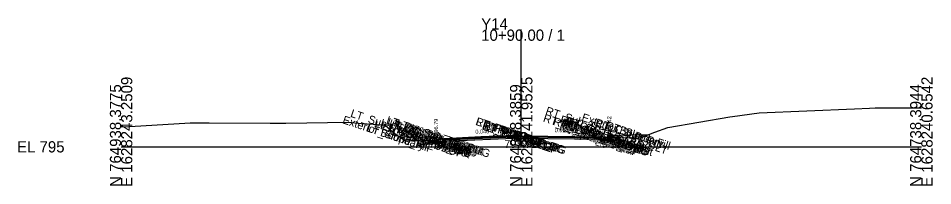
# Model space of a CAD drawing. Extents: x -26 to 1403, y -10 to 4517.
# Drawn here: x 1174.3 to 1402.8, y -9.7 to 32.1 of the extents above; entities that cross this region are included whole.
import ezdxf

# ---------------------------------------------------------------- set-up
doc = ezdxf.new("R2010")
doc.units = 0
for name, color, linetype in [('Default', 7, 'Continuous'), ('Exist CMT Pavement', 7, 'Continuous'), ('Exist Cross Section Cell', 7, 'Continuous'), ('Exist XS Center Line Elevation Label', 7, 'Continuous'), ('Exist XS Ground Line', 7, 'Continuous'), ('Prop CMT Conc Surface', 7, 'Continuous'), ('Prop CMT Concrete Structures', 7, 'Continuous'), ('Prop CMT Pvmt Course 1', 7, 'Continuous'), ('Prop CMT Pvmt Course 1 CG', 7, 'Continuous'), ('Prop CMT Pvmt Course 1 Wedge', 7, 'Continuous'), ('Prop CMT Pvmt Course 2', 7, 'Continuous'), ('Prop CMT Pvmt Course 2 Wedge', 7, 'Continuous'), ('Prop CMT Pvmt Course 3', 7, 'Continuous'), ('Prop CMT Pvmt Course 3 Wedge', 7, 'Continuous'), ('Prop CMT Pvmt Surface', 7, 'Continuous'), ('Prop CMT Pvmt Wedge Surface 1', 7, 'Continuous'), ('Prop CMT Pvmt Wedge Surface 2', 7, 'Continuous'), ('Prop CMT Pvmt Wedge Surface 3', 7, 'Continuous'), ('Prop CMT Slope Grass', 7, 'Continuous'), ('Prop CMT Subgrade Earthwork', 7, 'Continuous'), ('Prop XS Hydro Elevations', 7, 'Continuous'), ('Prop XS SE Text', 7, 'Continuous'), ('Scratch_Level_0', 7, 'Continuous')]:
    doc.layers.add(name, color=color, linetype=linetype)

msp = doc.modelspace()

# ---------------------------------------------------------------- linework, layer by layer
at = {"layer": 'Exist CMT Pavement'}
for points in [[(1300, 2.72), (1296.27, 2.75), (1289.94, 2.52), (1280.71, 2.02)], [(1300, 2.72), (1319.98, 2.52)]]:
    msp.add_lwpolyline(points, dxfattribs=at)
at = {"layer": 'Exist Cross Section Cell'}
for p, q in [((1300, 0), (1300, 29.25)), ((1200, 0), (1300, 0)), ((1300, 0), (1400, 0))]:
    msp.add_line(p, q, dxfattribs=at)
at = {"layer": 'Exist XS Ground Line'}
msp.add_lwpolyline([(1200, 4.98), (1202.22, 5.06), (1217.27, 5.96), (1221.97, 5.97), (1237.27, 5.88), (1241.16, 5.94), (1256.85, 6.11), (1260.03, 5.8), (1262.96, 5.64), (1266.02, 5.41), (1268.47, 3.22), (1270.61, 1.81), (1274.23, 1.49), (1277.23, 1.59), (1280.71, 2.02), (1289.94, 2.52), (1296.27, 2.75), (1300, 2.72), (1304.27, 2.67), (1319.98, 2.52), (1329.42, 2.12), (1329.8, 2.27), (1333.43, 3.65), (1336.63, 4.78), (1352.12, 7.46), (1352.8, 7.54), (1359.49, 8.5), (1383.26, 9.46), (1387.07, 9.68), (1388.46, 9.69), (1400, 9.75)], dxfattribs=at)
at = {"layer": 'Prop CMT Conc Surface'}
for points in [[(1278.71, 1.79), (1278.71, 2.29), (1278.21, 2.29)], [(1319.98, 2.52), (1321.98, 2.42)], [(1321.98, 2.42), (1321.98, 2.92), (1322.48, 2.92)], [(1280.71, 1.95), (1278.71, 1.79)]]:
    msp.add_lwpolyline(points, dxfattribs=at)
at = {"layer": 'Prop CMT Concrete Structures'}
for points in [[(1280.71, 1.95), (1278.71, 1.79), (1278.71, 2.29), (1278.21, 2.29)], [(1278.21, 2.29), (1278.21, 1.26), (1280.71, 1.36)], [(1319.98, 2.52), (1321.98, 2.42), (1321.98, 2.92), (1322.48, 2.92)], [(1322.48, 2.92), (1322.48, 1.91), (1319.98, 1.94)], [(1319.98, 1.94), (1319.98, 2.52)], [(1280.71, 1.36), (1280.71, 1.95)]]:
    msp.add_lwpolyline(points, dxfattribs=at)
at = {"layer": 'Prop CMT Pvmt Course 1'}
for points in [[(1300, 2.72), (1280.71, 1.95)], [(1280.71, 1.82), (1300, 2.59)], [(1300, 2.47), (1300, 2.72)], [(1300, 2.72), (1319.98, 2.52)], [(1300, 2.47), (1300, 2.72)], [(1300, 2.59), (1300, 2.47), (1300, 2.47)], [(1319.98, 2.4), (1300, 2.59)], [(1300, 2.59), (1300, 2.47), (1300, 2.47)], [(1319.98, 2.52), (1319.98, 2.27), (1319.98, 2.27), (1319.98, 2.4)], [(1280.71, 1.95), (1280.71, 1.7), (1280.71, 1.7), (1280.71, 1.82)]]:
    msp.add_lwpolyline(points, dxfattribs=at)
at = {"layer": 'Prop CMT Pvmt Course 1 CG'}
for points in [[(1280.71, 1.36), (1277.71, 1.24), (1277.36, 0.9)], [(1277.36, 0.9), (1280.71, 1.03)], [(1280.71, 1.03), (1280.71, 1.36)], [(1319.98, 1.94), (1322.98, 1.91), (1323.31, 1.57)], [(1319.98, 1.6), (1319.98, 1.94)], [(1323.31, 1.57), (1319.98, 1.6)]]:
    msp.add_lwpolyline(points, dxfattribs=at)
at = {"layer": 'Prop CMT Pvmt Course 1 Wedge'}
for points in [[(1300, 2.59), (1280.71, 1.82)], [(1300, 2.59), (1319.98, 2.4)]]:
    msp.add_lwpolyline(points, dxfattribs=at)
at = {"layer": 'Prop CMT Pvmt Course 2'}
for points in [[(1280.71, 1.36), (1280.71, 1.36), (1280.71, 1.7), (1280.71, 1.7)], [(1280.71, 1.7), (1280.71, 1.36)], [(1319.98, 1.94), (1319.98, 1.94), (1319.98, 2.27), (1319.98, 2.27)], [(1319.98, 2.27), (1319.98, 1.94)]]:
    msp.add_lwpolyline(points, dxfattribs=at)
at = {"layer": 'Prop CMT Pvmt Course 2 Wedge'}
for points in [[(1300, 2.47), (1280.71, 1.7)], [(1300, 2.47), (1319.98, 2.27)]]:
    msp.add_lwpolyline(points, dxfattribs=at)
at = {"layer": 'Prop CMT Pvmt Course 3'}
for points in [[(1280.71, 1.36), (1280.71, 1.36), (1280.71, 1.03), (1280.71, 1.03)], [(1280.71, 1.03), (1280.71, 1.36)], [(1319.98, 1.94), (1319.98, 1.94), (1319.98, 1.6), (1319.98, 1.6)], [(1319.98, 1.6), (1319.98, 1.94)]]:
    msp.add_lwpolyline(points, dxfattribs=at)
at = {"layer": 'Prop CMT Pvmt Course 3 Wedge'}
for points in [[(1300, 2.14), (1280.71, 1.36)], [(1300, 2.14), (1319.98, 1.94)]]:
    msp.add_lwpolyline(points, dxfattribs=at)
at = {"layer": 'Prop CMT Pvmt Surface'}
for points in [[(1300, 2.72), (1280.71, 1.95)], [(1300, 2.72), (1319.98, 2.52)]]:
    msp.add_lwpolyline(points, dxfattribs=at)
at = {"layer": 'Prop CMT Pvmt Wedge Surface 1'}
for points in [[(1300, 2.59), (1280.71, 1.82)], [(1300, 2.59), (1319.98, 2.4)], [(1319.98, 2.27), (1319.98, 2.52)], [(1319.98, 2.4), (1319.98, 2.27), (1319.98, 2.27)], [(1280.71, 1.7), (1280.71, 1.95)], [(1280.71, 1.82), (1280.71, 1.7), (1280.71, 1.7)]]:
    msp.add_lwpolyline(points, dxfattribs=at)
at = {"layer": 'Prop CMT Pvmt Wedge Surface 2'}
for points in [[(1300, 2.47), (1280.71, 1.7)], [(1300, 2.47), (1319.98, 2.27)], [(1319.98, 2.27), (1319.98, 2.52)], [(1280.71, 1.7), (1280.71, 1.95)]]:
    msp.add_lwpolyline(points, dxfattribs=at)
at = {"layer": 'Prop CMT Pvmt Wedge Surface 3'}
for points in [[(1319.98, 1.94), (1319.98, 2.52)], [(1300, 2.14), (1280.71, 1.36)], [(1280.71, 1.36), (1280.71, 1.95)], [(1300, 2.14), (1319.98, 1.94)]]:
    msp.add_lwpolyline(points, dxfattribs=at)
at = {"layer": 'Prop CMT Slope Grass'}
for points in [[(1278.21, 2.29), (1269.62, 2.46)], [(1322.48, 2.92), (1332.02, 3.11)]]:
    msp.add_lwpolyline(points, dxfattribs=at)
at = {"layer": 'Prop CMT Subgrade Earthwork'}
for points in [[(1280.71, 1.03), (1277.36, 0.9), (1275.92, 2.33)], [(1319.98, 1.6), (1319.96, 2.52)], [(1319.98, 1.6), (1323.31, 1.57), (1324.71, 2.96)], [(1280.71, 1.03), (1280.72, 2.02)], [(1280.71, 1.03), (1280.71, 1.03)], [(1319.98, 1.6), (1319.98, 1.6)]]:
    msp.add_lwpolyline(points, dxfattribs=at)

# ---------------------------------------------------------------- texts
at = {"layer": 'Default'}
msp.add_text('-', height=0.0001, dxfattribs=at).set_placement((1200, 0))
at = {"layer": 'Exist Cross Section Cell'}
for s, p in [('Y14', (1290, 29.25)), ('10+90.00 / 1', (1290, 26.45)), ('EL 795', (1174, -1.4))]:
    msp.add_text(s, height=2.8, dxfattribs=at).set_placement(p)
for s, p in [('E 1628243.2509', (1202.8, -10)), ('E 1628241.9525', (1302.8, -10)), ('E 1628240.6542', (1402.8, -10)), ('N 764938.3775', (1200, -10)), ('N 764838.3859', (1300, -10)), ('N 764738.3944', (1400, -10))]:
    msp.add_text(s, height=2.8, rotation=90, dxfattribs=at).set_placement(p)
at = {"layer": 'Exist XS Center Line Elevation Label'}
msp.add_text('797.72', height=2, dxfattribs=at).set_placement((1295.79, -0.28))
at = {"layer": 'Prop XS Hydro Elevations'}
for s, p in [('797.42', (1322.48, 3.42)), ('796.79', (1279.21, 2.79))]:
    msp.add_text(s, height=1, rotation=90, dxfattribs=at).set_placement(p)
at = {"layer": 'Prop XS SE Text'}
for s, rotation, p in [('0.010', 359.4271, (1308.37, 3.64)), ('0.040', 2.2906, (1288.56, 3.26))]:
    msp.add_text(s, height=1, rotation=rotation, dxfattribs=at).set_placement(p)
at = {"layer": 'Scratch_Level_0'}
for s, p in [('LT_Sub_Trench_Out_DLT', (1257.17, 7.53)), ('RT_Sub_Trench_Out_DLT', (1305.91, 8.18)), ('Exterior Boundary', (1255.18, 5.92)), ('LT_PV_Sub_Tie_Out', (1266.12, 5.84)), ('LT_CG_Top_Face', (1266.3, 5.37)), ('LT_CG_Top_BOC', (1266.77, 5.04)), ('RT_PV_IEEOP_EG', (1288.43, 5.52)), ('LT_PV_IEEOP_EG', (1288.48, 5.5)), ('RT_PV_Sub_Tie_Out', (1305.32, 6.35)), ('RT_PV_OEEOP_EG', (1307.8, 5.53)), ('RT_CG_Top_Face', (1309.53, 6.02)), ('RT_CG1_Shelf_Out', (1309.86, 5.23)), ('RT_CG_Top_Gut', (1310.45, 5.21)), ('RT_CG_Top_BOC', (1311, 5.69)), ('Exterior Boundary', (1314.93, 6.52)), ('RT_CSLP_Pnt', (1318.29, 5.2)), ('LT_Slope_Fill', (1261.23, 3.91)), ('LT_CSLP_Pnt', (1263.07, 4.56)), ('LT_CG1_Shelf_Out', (1264.63, 4.55)), ('LT_CG_Bot_BOC', (1266.8, 4.01)), ('LT_CG_Top_Gut', (1267.23, 4.56)), ('LT_Sub_OEOP', (1267.66, 3.08)), ('LT_PV_OEEOP_EG', (1268.57, 5.01)), ('LT_Sub_OEEOP', (1270.16, 3.49)), ('LT_PV2_OEEOP', (1270.25, 4.13)), ('LT_PV3_OEEOP', (1270.25, 3.8)), ('LT_PV1_OEEOP', (1270.78, 4.08)), ('LT_CG_Bot_IE', (1270.82, 3.61)), ('LT_Sub_OEOT', (1270.98, 3.22)), ('LT_PV2_OEOT', (1271.07, 3.86)), ('LT_PV3_OEOT', (1271.07, 3.52)), ('LT_PV1_OEOT', (1271.61, 3.93)), ('RT_PV2_IEEOP', (1290.11, 4.71)), ('RT_PV3_IEEOP', (1290.11, 4.38)), ('LT_PV2_IEEOP', (1290.15, 4.7)), ('LT_PV3_IEEOP', (1290.15, 4.37)), ('RT_PV1_IEEOP', (1290.65, 4.66)), ('LT_PV1_IEEOP', (1290.69, 4.64)), ('PV2_PGL', (1293.9, 3.45)), ('PV1_PGL', (1294.44, 3.52)), ('RT_Sub_OEEOP', (1309.38, 4.08)), ('RT_PV2_OEEOP', (1309.47, 4.72)), ('RT_PV3_OEEOP', (1309.47, 4.38)), ('RT_PV1_OEEOP', (1310.01, 4.66)), ('RT_CG_Bot_IE', (1310.05, 4.19)), ('RT_Sub_OEOT', (1310.2, 3.81)), ('RT_PV2_OEOT', (1310.29, 4.44)), ('RT_PV3_OEOT', (1310.29, 4.11)), ('RT_PV1_OEOT', (1310.83, 4.51)), ('RT_CG_Bot_BOC', (1311.03, 4.67)), ('RT_Sub_OEOP', (1313.57, 3.76)), ('RT_Slope_Fill', (1320.94, 4.52))]:
    msp.add_text(s, height=2, rotation=341.5651, dxfattribs=at).set_placement(p)

doc.saveas('drawing.dxf')
